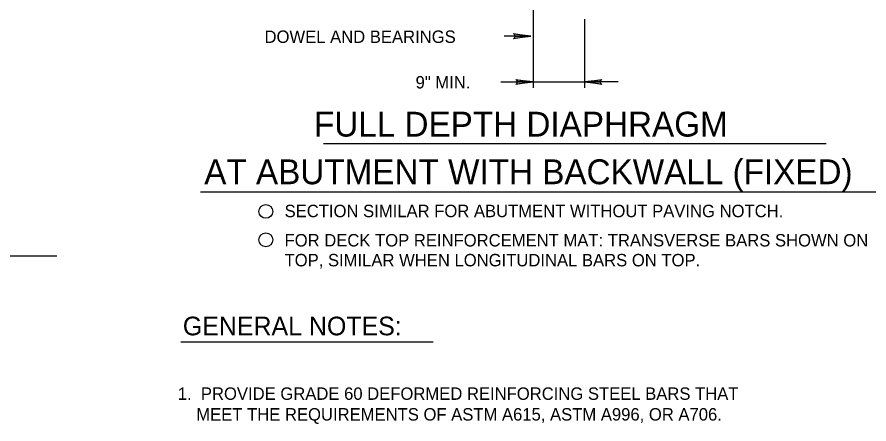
# Model space of a CAD drawing. Extents: x 638653 to 642302, y 298557 to 300414.
# Drawn here: x 639541.1 to 639746.7, y 300043.9 to 300142.1 of the extents above; entities that cross this region are included whole.
import ezdxf

# ---------------------------------------------------------------- set-up
doc = ezdxf.new("R2010")
doc.units = 0
doc.layers.add('1', color=7, linetype='Continuous')

msp = doc.modelspace()

# ---------------------------------------------------------------- linework, layer by layer
at = {"layer": '1'}
for p, q in [((639665.71, 300221.03), (639665.71, 300125.01)), ((639678.06, 300141.61), (639678.06, 300125.01)), ((639665.15, 300137.5), (639658.74, 300137.5)), ((639657.89, 300126.46), (639665.71, 300126.46)), ((639665.71, 300126.46), (639678.06, 300126.46)), ((639686.21, 300126.46), (639678.06, 300126.46)), ((639736.44, 300111.5), (639615.07, 300111.5)), ((639780.82, 300099.84), (639585.44, 300099.84)), ((639550.77, 300084.37), (639302.35, 300084.37)), ((639580.68, 300063.7), (639641.57, 300063.7))]:
    msp.add_line(p, q, dxfattribs=at)
for points in [[(639661.09, 300137.97), (639661.24, 300137.65), (639665.15, 300137.5), (639661.09, 300137.97), (639660.93, 300138.12), (639665.15, 300137.5), (639661.24, 300137.34), (639661.09, 300137.03), (639665.15, 300137.5), (639660.93, 300136.87), (639661.09, 300137.03)], [(639661.64, 300126.93), (639661.8, 300126.62), (639665.71, 300126.46), (639661.64, 300126.93), (639661.49, 300127.08), (639665.71, 300126.46), (639661.8, 300126.3), (639661.64, 300125.99), (639665.71, 300126.46), (639661.49, 300125.83), (639661.64, 300125.99)], [(639682.12, 300125.99), (639681.96, 300126.3), (639678.06, 300126.46), (639682.12, 300125.99), (639682.28, 300125.83), (639678.06, 300126.46), (639681.96, 300126.62), (639682.12, 300126.93), (639678.06, 300126.46), (639682.28, 300127.08), (639682.12, 300126.93)]]:
    msp.add_lwpolyline(points, dxfattribs=at)
for centre in [(639601.18, 300095.21), (639601.18, 300088.33)]:
    msp.add_circle(centre, 1.67, dxfattribs=at)

# ---------------------------------------------------------------- texts
for s, height, p in [('  DOWEL AND BEARINGS', 3, (639598.64, 300135.88)), ('9" MIN.', 3, (639637.32, 300124.88)), (' FULL DEPTH DIAPHRAGM', 6, (639610.57, 300113.27)), ('AT ABUTMENT WITH BACKWALL (FIXED)', 6, (639586.32, 300101.77)), ('SECTION SIMILAR FOR ABUTMENT WITHOUT PAVING NOTCH.', 3, (639605.71, 300093.81)), ('FOR DECK TOP REINFORCEMENT MAT: TRANSVERSE BARS SHOWN ON', 3, (639605.7, 300086.74)), ('TOP, SIMILAR WHEN LONGITUDINAL BARS ON TOP.', 3, (639605.7, 300081.94)), ('GENERAL NOTES:', 4.5, (639581.15, 300065.29)), ('1.  PROVIDE GRADE 60 DEFORMED REINFORCING STEEL BARS THAT ', 3, (639579.94, 300049.71)), ('    MEET THE REQUIREMENTS OF ASTM A615, ASTM A996, OR A706.', 3, (639579.94, 300044.71))]:
    msp.add_text(s, height=height, dxfattribs=at).set_placement(p)

doc.saveas('drawing.dxf')
